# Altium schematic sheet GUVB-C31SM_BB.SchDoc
size A
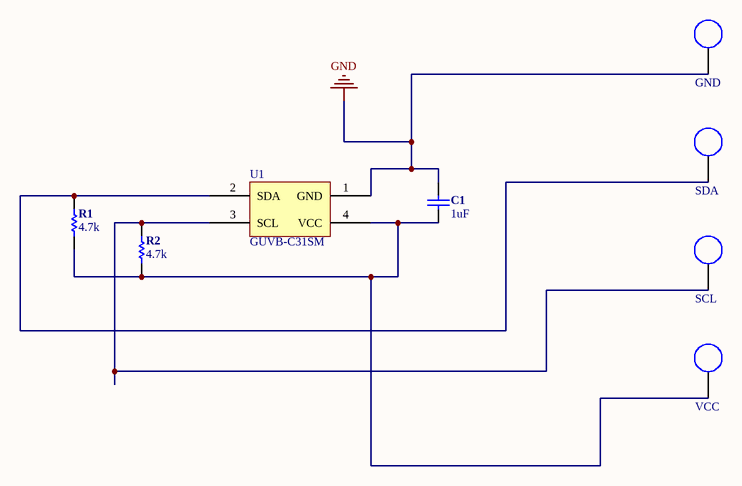
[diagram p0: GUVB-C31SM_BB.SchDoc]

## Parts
C1  1uF  [CAP-0805(2012)-R]
GND  S1751-46R  [S1751-46R]  (value not drawn)
R1  4.7k  [R-0805(2012)-R]
R2  4.7k  [R-0805(2012)-R]
SCL  S1751-46R  [S1751-46R]  (value not drawn)
SDA  S1751-46R  [S1751-46R]  (value not drawn)
U1  GUVB-C31SM  [GUVB-C31SM]
VCC  S1751-46R  [S1751-46R]  (value not drawn)

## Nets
GND: C1.1 GND.1 U1.1(GND)
NetC1_2: C1.2 R1.2 R2.2 U1.4(VCC) VCC.1
NetR1_1: R1.1 SDA.1 U1.2(SDA)
NetR2_1: R2.1 SCL.1 U1.3(SCL)

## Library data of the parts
C1 = C-0805(2012): ___ OHM ___ mW 0805(2012) SMD
GND SCL SDA VCC = S1751-46R: PC TEST POINT TIN SMD; Manufacturer: Harwin Inc.
R1 R2 = R-0805(2012): ___ OHM ___ mW 0805(2012) SMD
